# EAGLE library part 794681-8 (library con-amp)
Micro MATE-N-LOK Connectors grid 1.5mm Dual Row Through Hole Vertical Metal Through Hole Holddowns Source: ENG_CD_794681_E.pdf
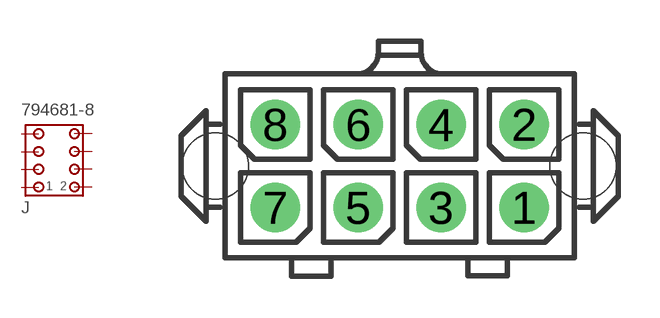
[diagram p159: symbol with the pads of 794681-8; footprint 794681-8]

Designator prefix J

## 794681-8 (MF: TYCO ELECTRONICS; MPN: 794681-8; OC_FARNELL: unknown; OC_NEWARK: 19H3754)  [794681-8]
1  1  pas
2  2  pas
3  3  pas
4  4  pas
5  5  pas
6  6  pas
7  7  pas
8  8  pas

## Footprint 794681-8 (pad centres in mm)
Micro MATE-N-LOK Connectors grid 1.5mm Dual Row Through Hole Vertical Metal Through Hole Holddowns Source: ENG_CD_794681_E.pdf
drill 1 pad 1.778 round: 1 4.5,-1.5; 2 4.5,1.5; 3 1.5,-1.5; 4 1.5,1.5; 5 -1.5,-1.5; 6 -1.5,1.5; 7 -4.5,-1.5; 8 -4.5,1.5
hole 2.4 at 6.63,0
hole 2.4 at -6.67,0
